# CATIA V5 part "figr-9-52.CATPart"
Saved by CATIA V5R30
Part number: Part1
Bounding box of the stored display mesh (mm): x -121 to 121, y -90 to 90, z -40 to 40
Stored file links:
  D:\PROJECTS\CATIA V56R 2020\Resources\Parts File\c09_catia_v5_6r2020_prt\figr-9-52.CATPart
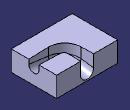
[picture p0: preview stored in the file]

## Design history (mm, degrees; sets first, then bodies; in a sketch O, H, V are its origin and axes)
Body1 (main body)
  Sketch1 on yz-plane, origin (0, 0, 0), H (0, 1, 0), V (0, 0, 1)
    line L1 (-90, 40) -> (90, 40)
    line L2 (90, 40) -> (90, -40)
    line L3 (90, -40) -> (-90, -40)
    line L4 (-90, -40) -> (-90, 40)
    axis line L5 (90, -40) -> (-90, 40)
    horizontal: L1 H, L3 H
    vertical: L2 V, L4 V
    midpoint: O L5
  Pad1: profile Sketch1, direction (1, 0, 0), length 121, mirrored extent
  Loft1: solid, Sections (Sketch4; Sketch3), Spine Sketch2, SectionCouplingPoints ({coupling CouplingPoints (vertex [element of Sketch4 | element of Sketch4]; vertex [element of Sketch3 | element of Sketch3])}; {coupling CouplingPoints (vertex [element of Sketch4 | element of Sketch4]; vertex [element of Sketch3 | element of Sketch3])}; {coupling CouplingPoints (vertex [element of Sketch4 | element of Sketch4]; vertex [element of Sketch3 | element of Sketch3])})
  Sketch2 on face of Pad1, origin (0, 0, 40), H (1, 0, 0), V (0, 1, 0)
    point P1 (121, 0)
    line L1 (121, 0) -> (40.984, 0)
    arc A1 centre (40.984, 40.984) radius 40.984 from (40.984, 0) to (0, 40.984) cw
    line L2 (0, 40.984) -> (0, 90)
    point P5 (0, 90)
    reference projected line E1 (121, 20) -> (121, -20) from edge of Sketch4
    reference projected line E2 (-25.9516, 90) -> (25.9516, 90) from edge of Sketch3
    coincidence: P1 H, P1 E1, P5 E2
    horizontal: L1 H
    tangency: A1 L1, L2 A1
    vertical: L2 V
  Sketch3 on face of Pad1, origin (0, 90, 0), H (-1, 0, 0), V (0, 0, 1)
    line L1 (-25.9516, 40) -> (-25.9516, -8.0968)
    arc A1 centre (0, -8.0968) radius 25.9516 from (-25.9516, -8.0968) to (25.9516, -8.0968) ccw
    point P3 (0, -8.0968)
    line L2 (25.9516, -8.0968) -> (25.9516, 40)
    line L3 (25.9516, 40) -> (-25.9516, 40)
    reference projected line E1 (121, 40) -> (-121, 40) from edge [face of Pad1 | face of Pad1]
    vertical: L1 V, L2 V
    tangency: A1 L1, L2 A1
    horizontal: L3 H
    coincidence: P3 V, L3 E1
  Sketch4 on face of Pad1, origin (121, 0, 0), H (0, 1, 0), V (0, 0, 1)
    line L1 (-20, 40) -> (-20, 21.9917)
    arc A1 centre (0, 21.9917) radius 20 from (-20, 21.9917) to (20, 21.9917) ccw
    point P3 (0, 21.9917)
    line L2 (20, 21.9917) -> (20, 40)
    line L3 (20, 40) -> (-20, 40)
    reference projected line E1 (90, 40) -> (-90, 40) from edge [face of Pad1 | face of Pad1]
    vertical: L1 V, L2 V
    tangency: A1 L1, L2 A1
    horizontal: L3 H
    coincidence: P3 V, L3 E1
